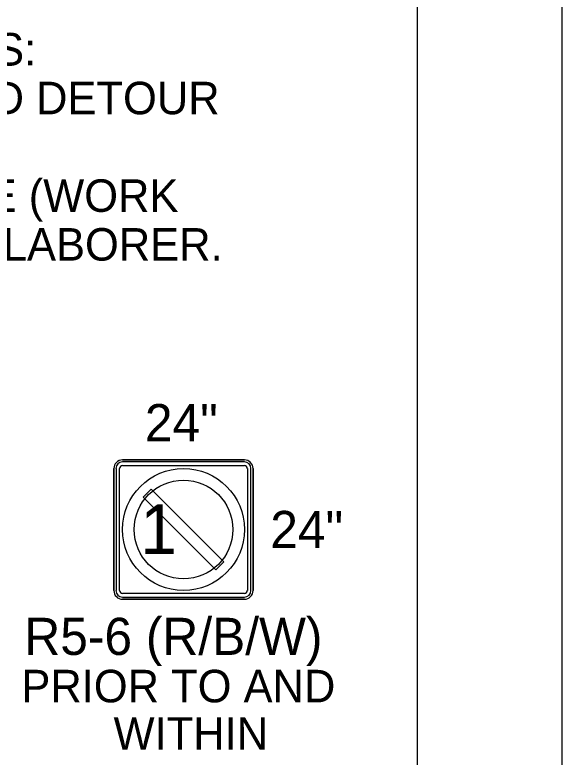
# Model space of a CAD drawing. Extents: x 99958 to 100176, y 99935 to 100011.
# Drawn here: x 100034.884 to 100036.062, y 100001.262 to 100002.86 of the extents above; entities that cross this region are included whole.
import ezdxf

# ---------------------------------------------------------------- set-up
doc = ezdxf.new("R2010")
doc.units = 0
for name, color, linetype in [('SH_GI_GeneralNotesBodyText', 7, 'Continuous'), ('SH_GI_PlotLimits', 7, 'Continuous'), ('SH_GI_SheetBorder', 7, 'Continuous'), ('TR_SN_ConstructionSigns', 7, 'Continuous')]:
    doc.layers.add(name, color=color, linetype=linetype)

msp = doc.modelspace()

# ---------------------------------------------------------------- linework, layer by layer
at = {"layer": 'SH_GI_PlotLimits'}
msp.add_lwpolyline([(100019.0625, 99999.6875), (100036.0625, 99999.6875), (100036.0625, 100010.6875), (100019.0625, 100010.6875)], close=True, dxfattribs=at)
at = {"layer": 'SH_GI_SheetBorder'}
msp.add_line((100035.75, 100010.375), (100035.75, 100000), dxfattribs=at)
at = {"layer": 'TR_SN_ConstructionSigns'}
for p, q in [((100035.3783, 100001.9019), (100035.1158, 100001.9019)), ((100035.1158, 100001.9019), (100035.3783, 100001.9019)), ((100035.3783, 100001.9019), (100035.1158, 100001.9019)), ((100035.3783, 100001.8972), (100035.1158, 100001.8972)), ((100035.1158, 100001.8894), (100035.3783, 100001.8894)), ((100035.0971, 100001.8831), (100035.0971, 100001.6206)), ((100035.0971, 100001.6206), (100035.0971, 100001.8831)), ((100035.0971, 100001.8831), (100035.0971, 100001.6206)), ((100035.1018, 100001.8831), (100035.1018, 100001.6206)), ((100035.1096, 100001.6206), (100035.1096, 100001.8831)), ((100035.3846, 100001.8831), (100035.3846, 100001.6206)), ((100035.3924, 100001.6206), (100035.3924, 100001.8831)), ((100035.3971, 100001.6206), (100035.3971, 100001.8831)), ((100035.3971, 100001.8831), (100035.3971, 100001.6206)), ((100035.3971, 100001.6206), (100035.3971, 100001.8831)), ((100035.3783, 100001.6144), (100035.1158, 100001.6144)), ((100035.1158, 100001.6066), (100035.3783, 100001.6066)), ((100035.1158, 100001.6019), (100035.3783, 100001.6019)), ((100035.3783, 100001.6019), (100035.1158, 100001.6019)), ((100035.1158, 100001.6019), (100035.3783, 100001.6019))]:
    msp.add_line(p, q, dxfattribs=at)
msp.add_lwpolyline([(100035.3305, 100001.6861), (100035.1813, 100001.8353), (100035.1778, 100001.8389), (100035.1601, 100001.8212), (100035.3128, 100001.6685), (100035.3164, 100001.6649), (100035.3341, 100001.6826), (100035.3305, 100001.6861)], dxfattribs=at)
for radius in [0.1313, 0.1062]:
    msp.add_circle((100035.2471, 100001.7519), radius, dxfattribs=at)
for centre, radius, start, end in [((100035.1158, 100001.8831), 0.0187, 90, 180), ((100035.1158, 100001.8831), 0.0187, 90, 180), ((100035.1158, 100001.8831), 0.0187, 90, 180), ((100035.3783, 100001.8831), 0.0187, 0, 90), ((100035.3783, 100001.8831), 0.0187, 0, 90), ((100035.3783, 100001.8831), 0.0187, 0, 90), ((100035.1158, 100001.8831), 0.0141, 90, 180), ((100035.1158, 100001.8831), 0.00625, 90, 180), ((100035.3783, 100001.8831), 0.0141, 0, 90), ((100035.3783, 100001.8831), 0.00625, 0, 90), ((100035.1158, 100001.6206), 0.0187, 180, 270), ((100035.1158, 100001.6206), 0.0187, 180, 270), ((100035.1158, 100001.6206), 0.0187, 180, 270), ((100035.1158, 100001.6206), 0.0141, 180, 270), ((100035.1158, 100001.6206), 0.00625, 180, 270), ((100035.3783, 100001.6206), 0.0141, 270, 0), ((100035.3783, 100001.6206), 0.00625, 270, 0), ((100035.3783, 100001.6206), 0.0187, 270, 0), ((100035.3783, 100001.6206), 0.0187, 270, 0), ((100035.3783, 100001.6206), 0.0187, 270, 0)]:
    msp.add_arc(centre, radius, start, end, dxfattribs=at)

# ---------------------------------------------------------------- texts
at = {"layer": 'SH_GI_GeneralNotesBodyText'}
for s, p in [('12. BICYCLIST ACCOMMODATIONS, WHERE FACILITY OPEN TO BICYCLES:', (100031.549, 100002.7506)), ('(A) BICYCLES PROHIBITED VIA R5-601 & R5-6 SIGNS. PROVIDE SIGNED DETOUR ', (100031.689, 100002.6456)), ('(B) BICYCLES PROHIBITED VIA R5-6 SIGN(S). PROVIDE FREE SHUTTLE (WORK ', (100031.689, 100002.4356)), ('TRUCK, VAN, OR BUS OK) + CONTACT INFORMATION/PHONE BOX/LABORER. ', (100031.839, 100002.3306))]:
    msp.add_text(s, height=0.07, rotation=360, dxfattribs=at).set_placement(p)
at = {"layer": 'TR_SN_ConstructionSigns'}
for s, height, p in [('24"', 0.08, (100035.164, 100001.9419)), ('24"', 0.08, (100035.434, 100001.7119)), ('R5-6 (R/B/W)', 0.08, (100034.9045, 100001.4819)), ('PRIOR TO AND', 0.07, (100034.898, 100001.3799)), ('WITHIN', 0.07, (100035.0965, 100001.2779))]:
    msp.add_text(s, height=height, rotation=360, dxfattribs=at).set_placement(p)
msp.add_text('1', height=0.1065, dxfattribs=at).set_placement((100035.1538, 100001.6994))

doc.saveas('drawing.dxf')
